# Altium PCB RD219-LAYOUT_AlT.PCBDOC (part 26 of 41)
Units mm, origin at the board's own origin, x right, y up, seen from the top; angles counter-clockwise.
Board outline 209.75 x 159.97 mm, 2 copper layers (TOP, BOTTOM), stack 0 mm thick; 398 components, 199 nets, 1469 pads, 0 vias.
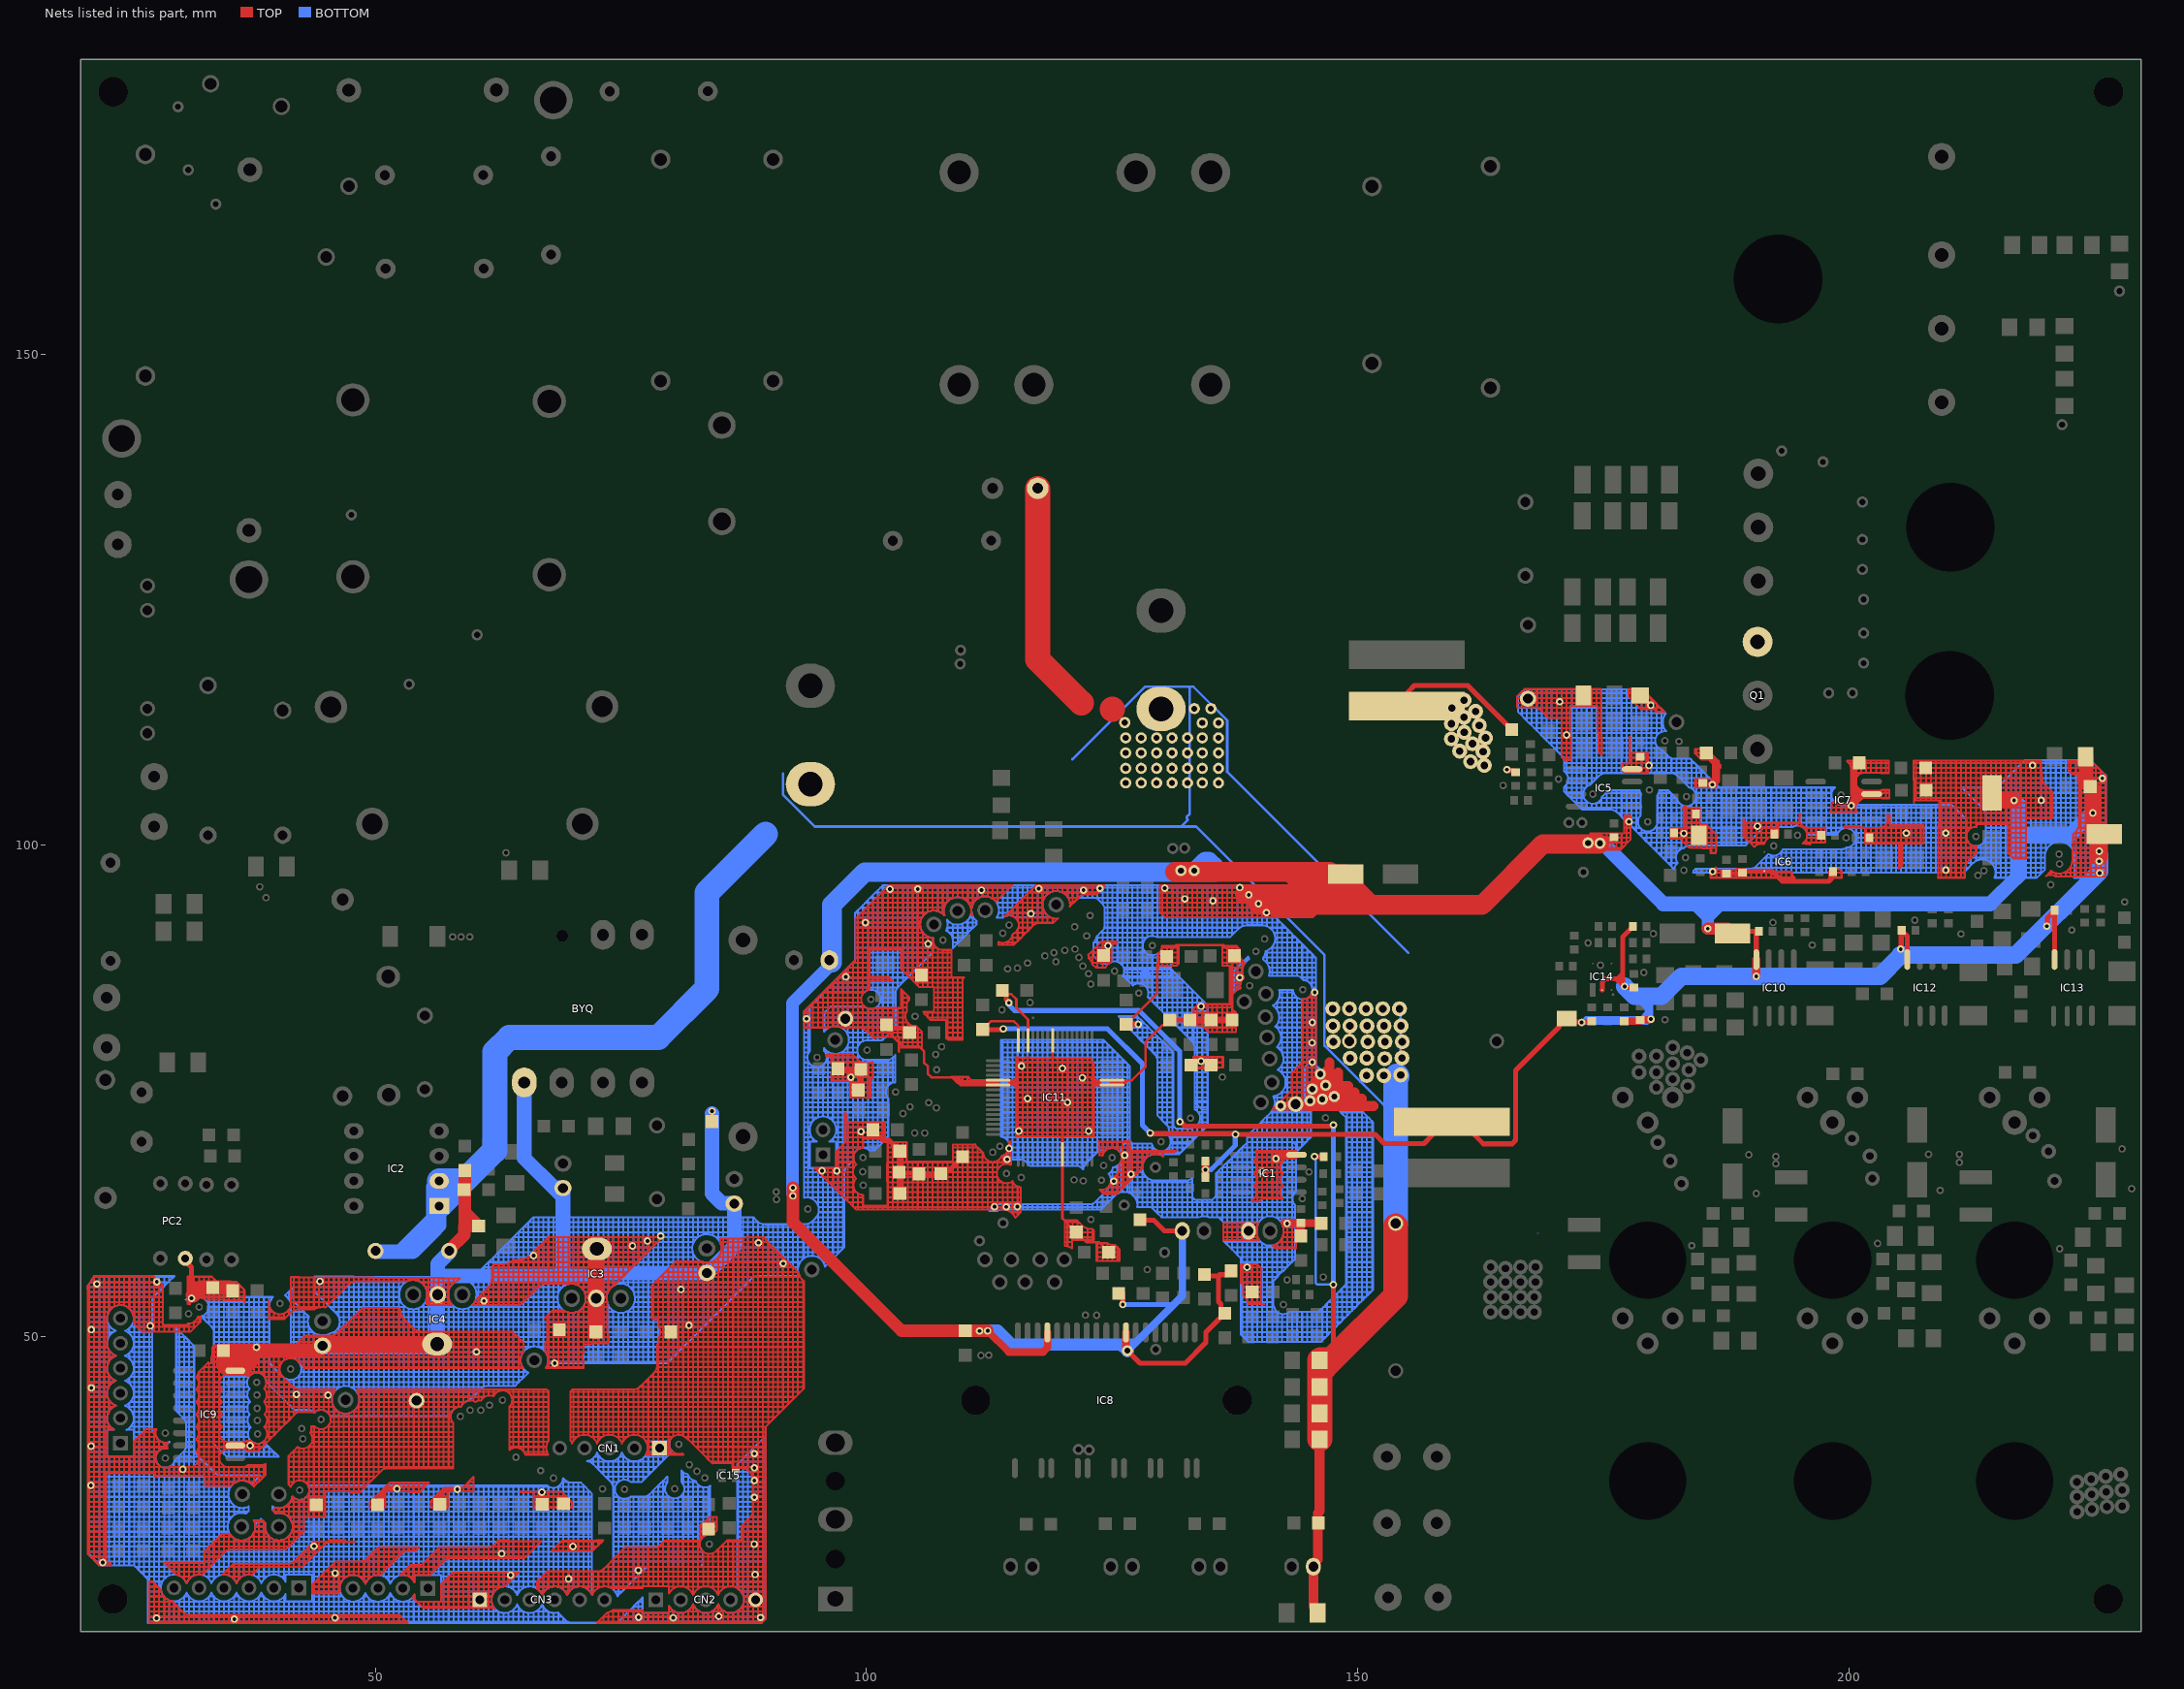
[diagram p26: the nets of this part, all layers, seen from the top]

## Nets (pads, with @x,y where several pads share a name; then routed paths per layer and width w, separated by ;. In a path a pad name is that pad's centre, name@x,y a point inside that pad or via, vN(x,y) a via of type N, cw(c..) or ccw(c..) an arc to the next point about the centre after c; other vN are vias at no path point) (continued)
GND: (continued)
  BOTTOM w0.203: 65.593,59.624 65.593,60.132 ; 65.593,59.624 66.101,59.624 ; 65.593,60.132 65.593,60.64 ; 65.593,60.132 66.101,60.132 ; 65.593,60.64 65.593,61.148 ; 65.593,60.64 66.101,60.64 ; 65.593,61.148 65.593,61.656 ; 65.593,61.148 66.101,61.148 ; 65.593,61.656 66.101,61.656 ; 65.593,61.656 66.101,62.164 ; 65.798,48.956 cw(c66.19,47.61) 66.101,49.009 ; 65.955,24.572 cw(c65.72,23.241) 66.093,24.54 cw(c65.72,23.241) 66.101,24.538 ; 65.955,24.572 66.101,24.572 ; 66.101,20.889 66.101,21.016 ; 66.101,20.889 66.609,20.889 ; 66.101,21.016 66.101,21.524 ; 66.101,21.016 66.609,21.016 ; 66.101,21.524 66.609,21.524 ; 66.101,21.524 66.101,21.944 ; 66.101,24.538 cw(c65.72,23.241) 66.607,24.261 cw(c65.72,23.241) 66.609,24.259 ; 66.101,24.538 66.101,24.572 ; 66.101,24.572 66.101,25.08 ; 66.101,24.572 66.609,24.572 ; 66.101,25.08 66.101,25.588 ; 66.101,25.08 66.609,25.08 ; 66.101,25.588 66.101,26.096 ; 66.101,25.588 66.609,25.588 ; 66.101,26.096 66.101,26.604 ; 66.101,26.096 66.609,26.096 ; 66.101,26.604 66.101,27.112 ; 66.101,26.604 66.609,26.604 ; 66.101,27.112 66.101,27.62 ; 66.101,27.112 66.609,27.112 ; 66.101,27.62 66.101,28.128 ; 66.101,27.62 66.609,27.62 ; 66.101,28.128 66.101,28.636 ; 66.101,28.128 66.609,28.128 ; 66.101,28.636 66.101,29.144 ; 66.101,28.636 66.609,28.636 ; 66.101,29.144 66.101,29.652 ; 66.101,29.144 66.609,29.144 ; 66.101,29.652 66.101,30.16 ; 66.101,29.652 66.609,29.652 ; 66.101,30.16 66.101,30.668 ; 66.101,30.16 66.609,30.16 ; 66.101,30.668 66.101,31.176 ; 66.101,30.668 66.609,30.668 ; 66.101,31.176 66.101,31.684 ; 66.101,31.176 66.609,31.176 ; 66.101,31.684 66.101,32.192 ; 66.101,31.684 66.609,31.684 ; 66.101,32.192 66.101,32.7 ; 66.101,32.192 66.609,32.192 ; 66.101,32.7 66.101,33.208 ; 66.101,32.7 66.609,32.7 ; 66.101,33.208 66.101,33.716 ; 66.101,33.208 66.609,33.208 ; 66.101,33.716 66.101,34.224 ; 66.101,33.716 66.609,33.716 ; 66.101,34.224 66.101,34.732 ; 66.101,34.224 pad.@66.609,34.224 ; 66.101,34.732 66.101,34.866 ; 66.101,34.732 66.609,34.732 ; 66.101,34.866 66.609,34.866 ; 66.101,49.009 cw(c66.19,47.61) 66.582,48.956 ; 66.101,49.009 66.101,49.464 ; 66.101,49.464 66.101,49.972 ; 66.101,49.464 66.609,49.464 ; 66.101,49.972 66.101,50.48 ; 66.101,49.972 66.609,49.972 ; 66.101,50.48 66.101,50.988 ; 66.101,50.48 66.609,50.48 ; 66.101,50.988 66.609,50.988 ; 66.101,50.988 66.101,51.496 ; 66.101,51.496 66.609,51.496 ; 66.101,51.496 66.101,52.004 ; 66.101,52.004 66.101,52.512 ; 66.101,52.004 66.609,52.004 ; 66.101,52.512 66.101,53.02 ; 66.101,52.512 66.609,52.512 ; 66.101,53.02 66.609,53.02 ; 66.101,53.02 66.101,53.528 ; 66.101,53.528 66.101,54.036 ; 66.101,53.528 66.609,53.528 ; 66.101,54.036 66.101,54.544 ; 66.101,54.036 66.609,54.036 ; 66.101,54.544 66.101,55.052 ; 66.101,54.544 66.609,54.544 ; 66.101,55.052 66.101,55.56 ; 66.101,55.052 66.609,55.052 ; 66.101,55.56 66.101,56.068 ; 66.101,55.56 66.609,55.56 ; 66.101,56.068 66.609,56.068 ; 66.101,56.068 66.101,56.195 66.101,56.576 ; 66.101,56.576 66.101,57.084 ; 66.101,56.576 66.609,56.576 ; 66.101,57.084 66.101,57.592 ; 66.101,57.084 66.609,57.084 ; 66.101,57.592 66.609,57.592 ; 66.101,57.592 pad.@66.101,58.1 ; pad.@66.101,58.1 66.609,58.1 ; pad.@66.101,58.1 pad.@66.101,58.608 ; pad.@66.101,58.608 66.101,59.116 ; pad.@66.101,58.608 66.609,58.608 ; 66.101,59.116 66.101,59.624 ; 66.101,59.116 66.609,59.116 ; 66.101,59.624 66.101,60.132 ; 66.101,59.624 66.609,59.624 ; 66.101,60.132 66.101,60.64 ; 66.101,60.132 66.609,60.132 ; 66.101,60.64 66.101,61.148 ; 66.101,60.64 66.609,60.64 ; 66.101,61.148 66.101,61.656 ; 66.101,61.148 66.609,61.148 ; 66.101,61.656 66.609,61.656 ; 66.101,61.656 66.101,62.164 ; 66.101,62.164 66.609,62.164 ; 66.582,48.956 cw(c66.19,47.61) 66.6,48.951 cw(c66.19,47.61) 66.609,48.948 ; 66.582,48.956 66.609,48.956 ; 66.609,20.889 66.609,21.016 ; 66.609,20.889 67.117,20.889 ; 66.609,21.016 66.609,21.524 ; 66.609,21.016 67.117,21.016 ; 66.609,21.524 66.609,22.032 ; 66.609,21.524 67.117,21.524 ; 66.609,22.032 67.117,22.032 ; 66.609,22.032 66.609,22.223 ; 66.609,22.223 ccw(c65.72,23.241) 66.876,22.54 ; 66.609,24.259 66.609,24.572 ; 66.609,24.572 66.609,25.08 ; 66.609,24.572 67.117,24.572 ; 66.609,25.08 66.609,25.588 ; 66.609,25.08 67.117,25.08 ; 66.609,25.588 66.609,26.096 ; 66.609,25.588 67.117,25.588 ; 66.609,26.096 66.609,26.604 ; 66.609,26.096 67.117,26.096 ; 66.609,26.604 66.609,27.112 ; 66.609,26.604 67.117,26.604 ; 66.609,27.112 66.609,27.62 ; 66.609,27.112 67.117,27.112 ; 66.609,27.62 66.609,28.128 ; 66.609,27.62 67.117,27.62 ; 66.609,28.128 66.609,28.636 ; 66.609,28.128 67.117,28.128 ; 66.609,28.636 66.609,29.144 ; 66.609,28.636 67.117,28.636 ; 66.609,29.144 66.609,29.652 ; 66.609,29.144 67.117,29.144 ; 66.609,29.652 66.609,30.16 ; 66.609,29.652 67.117,29.652 ; 66.609,30.16 66.609,30.668 ; 66.609,30.16 67.117,30.16 ; 66.609,30.668 66.609,31.176 ; 66.609,30.668 67.117,30.668 ; 66.609,31.176 66.609,31.684 ; 66.609,31.176 67.117,31.176 ; 66.609,31.684 66.609,32.192 ; 66.609,31.684 67.117,31.684 ; 66.609,32.192 66.609,32.7 ; 66.609,32.192 67.117,32.192 ; 66.609,32.7 66.609,33.208 ; 66.609,32.7 67.117,32.7 ; 66.609,33.208 66.609,33.716 ; 66.609,33.208 67.117,33.208 ; 66.609,33.716 pad.@66.609,34.224 ; 66.609,33.716 67.117,33.716 ; pad.@66.609,34.224 66.609,34.732 ; pad.@66.609,34.224 pad.@67.117,34.224 ; 66.609,34.732 66.609,34.866 ; 66.609,34.732 67.117,34.732 ; 66.609,34.866 67.117,34.866 ; 66.609,48.948 cw(c66.19,47.61) 67.11,48.668 cw(c66.19,47.61) 67.117,48.662 ; 66.609,48.948 66.609,48.956 ; 66.609,48.956 67.117,48.956 ; 66.609,48.956 66.609,49.464 ; 66.609,49.464 66.609,49.972 ; 66.609,49.464 67.117,49.464 ; 66.609,49.972 66.609,50.48 ; 66.609,49.972 67.117,49.972 ; 66.609,50.48 66.609,50.988 ; 66.609,50.48 67.117,50.48 ; 66.609,50.988 66.609,51.496 ; 66.609,50.988 67.117,50.988 ; 66.609,51.496 66.609,52.004 ; 66.609,51.496 67.117,51.496 ; 66.609,52.004 66.609,52.512 ; 66.609,52.004 67.117,52.004 ; 66.609,52.512 66.609,53.02 ; 66.609,52.512 67.117,52.512 ; 66.609,53.02 66.609,53.528 ; 66.609,53.02 67.117,53.02 ; 66.609,53.528 66.609,54.036 ; 66.609,53.528 67.117,53.528 ; 66.609,54.036 66.609,54.544 ; 66.609,54.036 67.117,54.036 ; 66.609,54.544 66.609,55.052 ; 66.609,54.544 67.117,54.544 ; 66.609,55.052 66.609,55.56 ; 66.609,55.052 67.117,55.052 ; 66.609,55.56 66.609,56.068 ; 66.609,55.56 67.117,55.56 ; 66.609,56.068 66.609,56.195 66.609,56.576 ; 66.609,56.068 67.117,56.068 ; 66.609,56.576 66.609,57.084 ; 66.609,56.576 67.117,56.576 ; 66.609,57.084 66.609,57.592 ; 66.609,57.084 67.117,57.084 ; 66.609,57.592 66.609,58.1 ; 66.609,57.592 67.117,57.592 ; 66.609,58.1 66.609,58.608 ; 66.609,58.1 67.117,58.1 ; 66.609,58.608 66.609,59.116 ; 66.609,58.608 67.117,58.608 ; 66.609,59.116 66.609,59.624 ; 66.609,59.116 67.117,59.116 ; 66.609,59.624 66.609,60.132 ; 66.609,59.624 67.117,59.624 ; 66.609,60.132 66.609,60.64 ; 66.609,60.132 67.117,60.132 ; 66.609,60.64 66.609,61.148 ; 66.609,60.64 67.117,60.64 ; 66.609,61.148 66.609,61.656 ; 66.609,61.148 67.117,61.148 ; 66.609,61.656 66.609,62.164 ; 66.609,61.656 67.117,61.656 ; 66.609,62.164 67.117,62.164 ; 66.876,22.54 ccw(c65.72,23.241) 66.879,22.545 ccw(c65.72,23.241) 66.99,22.779 ccw(c68.26,23.241) 67.104,22.54 ; 66.876,22.54 67.104,22.54 ; 67.104,22.54 ccw(c68.26,23.241) 67.114,22.525 ccw(c68.26,23.241) 67.117,22.52 ; 67.117,20.889 67.117,21.016 ; 67.117,20.889 67.625,20.889 ; 67.117,21.016 67.117,21.524 ; 67.117,21.016 67.625,21.016 ; 67.117,21.524 67.117,22.032 ; 67.117,21.524 67.625,21.524 ; 67.117,22.032 67.625,22.032 ; 67.117,22.032 67.117,22.52 ; 67.117,22.52 ccw(c68.26,23.241) 67.625,22.048 67.625,22.032 ; 67.117,24.064 67.117,24.572 ; 67.117,24.064 67.188,24.064 ; 67.117,24.572 67.117,25.08 ; 67.117,24.572 67.625,24.572 ; 67.117,25.08 67.117,25.588 ; 67.117,25.08 67.625,25.08 ; 67.117,25.588 67.117,26.096 ; 67.117,25.588 67.625,25.588 ; 67.117,26.096 67.117,26.604 ; 67.117,26.096 67.625,26.096 ; 67.117,26.604 67.625,26.604 ; 67.117,26.604 67.117,27.112 ; 67.117,27.112 67.117,27.62 ; 67.117,27.112 67.625,27.112 ; 67.117,27.62 67.117,28.128 ; 67.117,27.62 67.625,27.62 ; 67.117,28.128 67.117,28.636 ; 67.117,28.128 67.625,28.128 ; 67.117,28.636 67.117,29.144 ; 67.117,28.636 67.625,28.636 ; 67.117,29.144 67.117,29.652 ; 67.117,29.144 67.625,29.144 ; 67.117,29.652 67.117,30.16 ; 67.117,29.652 67.625,29.652 ; 67.117,30.16 67.117,30.668 ; 67.117,30.16 67.625,30.16 ; 67.117,30.668 67.625,30.668 ; 67.117,30.668 67.117,31.176 ; 67.117,31.176 67.117,31.684 ; 67.117,31.176 67.625,31.176 ; 67.117,31.684 67.117,32.192 ; 67.117,31.684 67.625,31.684 ; 67.117,32.192 67.625,32.192 ; 67.117,32.192 67.117,32.7 ; 67.117,32.7 67.117,33.208 ; 67.117,32.7 67.625,32.7 ; 67.117,33.208 67.117,33.716 ; 67.117,33.208 67.625,33.208 ; 67.117,33.716 67.625,33.716 ; 67.117,33.716 pad.@67.117,34.224 ; pad.@67.117,34.224 67.625,34.224 ; pad.@67.117,34.224 67.117,34.732 ; 67.117,34.732 67.625,34.732 ; 67.117,34.732 67.117,34.866 ; 67.117,48.662 cw(c66.19,47.61) 67.309,48.454 cw(c66.19,47.61) 67.314,48.448 ; 67.117,48.662 67.117,48.956 ; 67.117,48.956 67.117,49.464 ; 67.117,48.956 67.625,48.956 ; 67.117,49.464 67.117,49.972 ; 67.117,49.464 67.625,49.464 ; 67.117,49.972 67.117,50.48 ; 67.117,49.972 67.625,49.972 ; 67.117,50.48 67.117,50.988 ; 67.117,50.48 67.625,50.48 ; 67.117,50.988 67.625,50.988 ; 67.117,50.988 67.117,51.496 ; 67.117,51.496 67.625,51.496 ; 67.117,51.496 67.117,52.004 ; 67.117,52.004 67.117,52.512 ; 67.117,52.004 67.625,52.004 ; 67.117,52.512 67.117,53.02 ; 67.117,52.512 67.625,52.512 ; 67.117,53.02 67.625,53.02 ; 67.117,53.02 67.117,53.528 ; 67.117,53.528 67.117,54.036 ; 67.117,53.528 67.625,53.528 ; 67.117,54.036 67.625,54.036 ; 67.117,54.036 67.117,54.544 ; 67.117,54.544 67.625,54.544 ; 67.117,54.544 67.117,55.052 ; 67.117,55.052 67.625,55.052 ; 67.117,55.052 67.117,55.56 ; 67.117,55.56 67.117,56.068 ; 67.117,55.56 67.625,55.56 ; 67.117,56.068 67.625,56.068 ; 67.117,56.068 67.117,56.195 67.117,56.576 ; 67.117,56.576 67.625,56.576 ; 67.117,56.576 67.117,57.084 ; 67.117,57.084 67.625,57.084 ; 67.117,57.084 67.117,57.592 ; 67.117,57.592 67.625,57.592 ; 67.117,57.592 67.117,58.1 ; 67.117,58.1 67.117,58.608 ; 67.117,58.1 67.625,58.1 ; 67.117,58.608 67.117,59.116 ; 67.117,58.608 67.625,58.608 ; 67.117,59.116 67.117,59.624 ; 67.117,59.116 67.625,59.116 ; 67.117,59.624 67.117,60.132 ; 67.117,59.624 67.625,59.624 ; 67.117,60.132 67.625,60.132 ; 67.117,60.132 67.117,60.64 ; 67.117,60.64 67.625,60.64 ; 67.117,60.64 67.117,61.148 ; 67.117,61.148 67.117,61.656 ; 67.117,61.148 67.625,61.148 ; 67.117,61.656 67.625,61.656 ; 67.117,61.656 67.117,62.164 ; 67.117,62.164 67.625,62.164 ; 67.188,24.064 cw(c68.26,23.241) 67.625,24.434 ; 67.314,48.448 cw(c66.19,47.61) 67.55,47.949 cw(c66.19,47.61) 67.552,47.94 ; 67.314,48.448 67.625,48.448 ; 67.552,47.94 cw(c66.19,47.61) 67.58,47.432 ; 67.552,47.94 67.625,47.94 ; 67.58,47.432 cw(c66.19,47.61) 67.561,47.319 67.625,47.319 ; 67.58,47.432 67.625,47.432 ; 67.625,20.889 67.625,21.016 ; 67.625,20.889 68.133,20.889 ; 67.625,21.016 67.625,21.524 ; 67.625,21.016 68.133,21.016 ; 67.625,21.524 67.625,22.032 ; 67.625,21.524 68.133,21.524 ; 67.625,22.032 67.656,22.032 ; 67.625,24.434 cw(c68.26,23.241) 68.025,24.572 ; 67.625,24.434 67.625,24.572 ; 67.625,24.572 67.625,25.08 ; 67.625,24.572 68.025,24.572 ; 67.625,25.08 67.625,25.588 ; 67.625,25.08 68.133,25.08 ; 67.625,25.588 67.625,26.096 ; 67.625,25.588 68.133,25.588 ; 67.625,26.096 67.625,26.604 ; 67.625,26.096 68.133,26.096 ; 67.625,26.604 68.133,26.604 ; 67.625,26.604 67.625,27.112 ; 67.625,27.112 67.625,27.62 ; 67.625,27.112 68.133,27.112 ; 67.625,27.62 67.625,28.128 ; 67.625,27.62 68.133,27.62 ; 67.625,28.128 67.625,28.636 ; 67.625,28.128 68.133,28.128 ; 67.625,28.636 67.625,29.144 ; 67.625,28.636 68.133,28.636 ; 67.625,29.144 67.625,29.652 ; 67.625,29.144 68.133,29.144 ; 67.625,29.652 67.625,30.16 ; 67.625,29.652 68.133,29.652 ; 67.625,30.16 67.625,30.668 ; 67.625,30.16 68.133,30.16 ; 67.625,30.668 68.133,30.668 ; 67.625,30.668 67.625,31.176 ; 67.625,31.176 67.625,31.684 ; 67.625,31.176 68.133,31.176 ; 67.625,31.684 67.625,32.192 ; 67.625,31.684 68.133,31.684 ; 67.625,32.192 67.625,32.7 ; 67.625,32.192 68.133,32.192 ; 67.625,32.7 67.625,33.208 ; 67.625,32.7 68.133,32.7 ; 67.625,33.208 67.625,33.716 ; 67.625,33.208 68.133,33.208 ; 67.625,33.716 67.625,34.224 ; 67.625,33.716 68.133,33.716 ; 67.625,34.224 68.133,34.224 ; 67.625,34.224 67.625,34.732 ; 67.625,34.732 67.708,34.732 ; 67.625,34.732 67.625,34.777 ; 67.625,34.777 ccw(c68.133,35.618) 67.708,34.732 ; 67.625,47.319 67.625,47.432 ; 67.625,47.319 pad.@68.133,47.319 ; 67.625,47.432 67.625,47.94 ; 67.625,47.432 pad.@68.133,47.432 ; 67.625,47.94 67.625,48.448 ; 67.625,47.94 68.133,47.94 ; 67.625,48.448 67.625,48.956 ; 67.625,48.448 68.133,48.448 ; 67.625,48.956 67.625,49.464 ; 67.625,48.956 68.133,48.956 ; 67.625,49.464 67.625,49.972 ; 67.625,49.464 68.133,49.464 ; 67.625,49.972 67.625,50.48 ; 67.625,49.972 68.133,49.972 ; 67.625,50.48 67.625,50.988 ; 67.625,50.48 68.133,50.48 ; 67.625,50.988 67.625,51.496 ; 67.625,50.988 68.133,50.988 ; 67.625,51.496 67.625,52.004 ; 67.625,51.496 68.133,51.496 ; 67.625,52.004 67.625,52.512 ; 67.625,52.004 68.133,52.004 ; 67.625,52.512 67.625,53.02 ; 67.625,52.512 68.133,52.512 ; 67.625,53.02 68.133,53.02 ; 67.625,53.02 67.625,53.528 ; 67.625,53.528 67.625,54.036 ; 67.625,53.528 68.133,53.528 ; 67.625,54.036 67.625,54.544 ; 67.625,54.036 68.133,54.036 ; 67.625,54.544 67.625,55.052 ; 67.625,54.544 68.133,54.544 ; 67.625,55.052 67.625,55.56 ; 67.625,55.052 68.133,55.052 ; 67.625,55.56 67.625,56.068 ; 67.625,55.56 68.133,55.56 ; 67.625,56.068 68.133,56.068 ; 67.625,56.068 67.625,56.195 67.625,56.576 ; 67.625,56.576 68.133,56.576 ; 67.625,56.576 67.625,57.084 ; 67.625,57.084 67.625,57.592 ; 67.625,57.084 68.133,57.084 ; 67.625,57.592 68.133,57.592 ; 67.625,57.592 67.625,58.1 ; 67.625,58.1 67.625,58.608 ; 67.625,58.1 68.133,58.1 ; 67.625,58.608 67.625,59.116 ; 67.625,58.608 68.133,58.608 ; 67.625,59.116 67.625,59.624 ; 67.625,59.116 68.133,59.116 ; 67.625,59.624 67.625,60.132 ; 67.625,59.624 68.133,59.624 ; 67.625,60.132 67.625,60.64 ; 67.625,60.132 68.133,60.132 ; 67.625,60.64 67.625,61.148 ; 67.625,60.64 68.133,60.64 ; 67.625,61.148 67.625,61.656 ; 67.625,61.148 68.133,61.148 ; 67.625,61.656 67.625,62.164 ; 67.625,61.656 68.133,61.656 ; 67.625,62.164 68.133,62.164 ; 67.656,22.032 ccw(c68.26,23.241) 68.133,21.895 ; 67.708,34.732 ccw(c68.133,35.618) 68.133,34.635 ; 68.025,24.572 cw(c68.26,23.241) 68.133,24.587 ; 68.133,20.889 68.641,20.889 ; 68.133,20.889 68.133,21.016 ; 68.133,21.016 68.641,21.016 ; 68.133,21.016 68.133,21.524 ; 68.133,21.524 68.641,21.524 ; 68.133,21.524 68.133,21.895 ; 68.133,21.895 ccw(c68.26,23.241) 68.142,21.895 ccw(c68.26,23.241) 68.599,21.933 ; 68.133,24.587 cw(c68.26,23.241) 68.495,24.572 ; 68.133,24.587 68.133,25.08 ; 68.133,25.08 68.133,25.588 ; 68.133,25.08 68.641,25.08 ; 68.133,25.588 68.133,26.096 ; 68.133,25.588 68.641,25.588 ; 68.133,26.096 68.133,26.604 ; 68.133,26.096 68.641,26.096 ; 68.133,26.604 68.133,27.112 ; 68.133,26.604 68.641,26.604 ; 68.133,27.112 68.133,27.62 ; 68.133,27.112 68.641,27.112 ; 68.133,27.62 68.133,28.128 ; 68.133,27.62 68.641,27.62 ; 68.133,28.128 68.133,28.636 ; 68.133,28.128 68.641,28.128 ; 68.133,28.636 68.133,29.144 ; 68.133,28.636 68.641,28.636 ; 68.133,29.144 68.133,29.652 ; 68.133,29.144 68.641,29.144 ; 68.133,29.652 68.133,30.16 ; 68.133,29.652 68.641,29.652 ; 68.133,30.16 68.133,30.668 ; 68.133,30.16 68.641,30.16 ; 68.133,30.668 68.133,31.176 ; 68.133,30.668 68.641,30.668 ; 68.133,31.176 68.133,31.684 ; 68.133,31.176 68.641,31.176 ; 68.133,31.684 68.133,32.192 ; 68.133,31.684 68.641,31.684 ; 68.133,32.192 68.133,32.7 ; 68.133,32.192 68.641,32.192 ; 68.133,32.7 68.133,33.208 ; 68.133,32.7 68.641,32.7 ; 68.133,33.208 68.133,33.716 ; 68.133,33.208 68.641,33.208 ; 68.133,33.716 68.133,34.224 ; 68.133,33.716 68.641,33.716 ; 68.133,34.224 68.641,34.224 ; 68.133,34.224 68.133,34.635 ; 68.133,34.635 ccw(c68.133,35.618) 68.558,34.732 ; pad.@68.133,47.319 pad.@68.133,47.432 ; pad.@68.133,47.319 68.641,47.319 ; pad.@68.133,47.432 68.133,47.94 ; pad.@68.133,47.432 68.641,47.432 ; 68.133,47.94 68.133,48.448 ; 68.133,47.94 68.641,47.94 ; 68.133,48.448 68.133,48.956 ; 68.133,48.448 68.641,48.448 ; 68.133,48.956 68.133,49.464 ; 68.133,48.956 68.641,48.956 ; 68.133,49.464 68.133,49.972 ; 68.133,49.464 68.641,49.464 ; 68.133,49.972 68.133,50.48 ; 68.133,49.972 68.641,49.972 ; 68.133,50.48 68.133,50.988 ; 68.133,50.48 68.641,50.48 ; 68.133,50.988 68.133,51.496 ; 68.133,50.988 68.641,50.988 ; 68.133,51.496 68.133,52.004 ; 68.133,51.496 68.641,51.496 ; 68.133,52.004 68.133,52.512 ; 68.133,52.004 68.641,52.004 ; 68.133,52.512 68.133,53.02 ; 68.133,52.512 68.641,52.512 ; 68.133,53.02 68.133,53.528 ; 68.133,53.02 68.641,53.02 ; 68.133,53.528 68.133,54.036 ; 68.133,53.528 68.6,53.528 ; 68.133,54.036 68.133,54.544 ; 68.133,54.036 68.565,54.036 ; 68.133,54.544 68.641,54.544 ; 68.133,54.544 68.133,55.052 ; 68.133,55.052 68.641,55.052 ; 68.133,55.052 68.133,55.56 ; 68.133,55.56 68.133,56.068 ; 68.133,55.56 68.641,55.56 ; 68.133,56.068 68.641,56.068 ; 68.133,56.068 68.133,56.195 68.133,56.576 ; 68.133,56.576 68.641,56.576 ; 68.133,56.576 68.133,57.084 ; 68.133,57.084 68.641,57.084 ; 68.133,57.084 68.133,57.592 ; 68.133,57.592 68.641,57.592 ; 68.133,57.592 68.133,58.1 ; 68.133,58.1 68.133,58.608 ; 68.133,58.1 68.641,58.1 ; 68.133,58.608 68.133,59.116 ; 68.133,58.608 68.641,58.608 ; 68.133,59.116 68.133,59.624 ; 68.133,59.116 68.641,59.116 ; 68.133,59.624 68.133,60.132 ; 68.133,59.624 68.641,59.624 ; 68.133,60.132 68.641,60.132 ; 68.133,60.132 68.133,60.64 ; 68.133,60.64 68.641,60.64 ; 68.133,60.64 68.133,61.148 ; 68.133,61.148 68.133,61.656 ; 68.133,61.148 68.641,61.148 ; 68.133,61.656 68.641,61.656 ; 68.133,61.656 68.133,62.164 ; 68.133,62.164 68.641,62.164 ; 68.495,24.572 cw(c68.26,23.241) 68.633,24.54 cw(c68.26,23.241) 68.641,24.538 ; 68.495,24.572 68.641,24.572 ; 68.558,34.732 ccw(c68.133,35.618) 68.639,34.776 ccw(c68.133,35.618) 68.641,34.777 ; 68.558,34.732 68.641,34.732 ; 68.565,54.036 ccw(c69.991,53.973) 68.564,53.973 68.564,53.846 ccw(c69.991,53.846) 68.6,53.528 ; 68.565,54.036 cw(c69.991,53.973) 68.641,54.435 ; 68.599,21.933 69.008,21.524 ; 68.6,53.528 ccw(c69.991,53.846) 68.641,53.383 ; 68.641,20.889 68.641,21.016 ; 68.641,20.889 69.149,20.889 ; 68.641,21.016 68.641,21.524 ; 68.641,21.016 69.149,21.016 ; 68.641,21.524 69.008,21.524 ; 68.641,24.538 cw(c68.26,23.241) 69.149,24.259 ; 68.641,24.538 68.641,24.572 ; 68.641,24.572 68.641,25.08 ; 68.641,24.572 69.149,24.572 ; 68.641,25.08 68.641,25.588 ; 68.641,25.08 69.149,25.08 ; 68.641,25.588 68.641,26.096 ; 68.641,25.588 69.149,25.588 ; 68.641,26.096 68.641,26.604 ; 68.641,26.096 69.149,26.096 ; 68.641,26.604 69.149,26.604 ; 68.641,26.604 68.641,27.112 ; 68.641,27.112 68.641,27.62 ; 68.641,27.112 69.149,27.112 ; 68.641,27.62 68.641,28.128 ; 68.641,27.62 69.149,27.62 ; 68.641,28.128 68.641,28.636 ; 68.641,28.128 69.149,28.128 ; 68.641,28.636 68.641,29.144 ; 68.641,28.636 69.149,28.636 ; 68.641,29.144 68.641,29.652 ; 68.641,29.144 69.149,29.144 ; 68.641,29.652 68.641,30.16 ; 68.641,29.652 69.149,29.652 ; 68.641,30.16 68.641,30.668 ; 68.641,30.16 69.149,30.16 ; 68.641,30.668 69.149,30.668 ; 68.641,30.668 68.641,31.176 ; 68.641,31.176 68.641,31.684 ; 68.641,31.176 69.149,31.176 ; 68.641,31.684 68.641,32.192 ; 68.641,31.684 69.149,31.684 ; 68.641,32.192 69.149,32.192 ; 68.641,32.192 68.641,32.7 ; 68.641,32.7 68.641,33.208 ; 68.641,32.7 69.149,32.7 ; 68.641,33.208 68.641,33.716 ; 68.641,33.208 69.149,33.208 ; 68.641,33.716 68.641,34.224 ; 68.641,33.716 69.149,33.716 ; 68.641,34.224 69.149,34.224 ; 68.641,34.224 68.641,34.732 ; 68.641,34.732 69.149,34.732 ; 68.641,34.732 68.641,34.777 ; 68.641,34.777 ccw(c68.133,35.618) 69.038,35.234 ccw(c68.133,35.618) 69.04,35.24 ; 68.641,47.319 68.641,47.432 ; 68.641,47.319 69.149,47.319 ; 68.641,47.432 68.641,47.94 ; 68.641,47.432 69.149,47.432 ; 68.641,47.94 68.641,48.448 ; 68.641,47.94 69.149,47.94 ; 68.641,48.448 68.641,48.956 ; 68.641,48.448 69.149,48.448 ; 68.641,48.956 68.641,49.464 ; 68.641,48.956 69.149,48.956 ; 68.641,49.464 68.641,49.972 ; 68.641,49.464 69.149,49.464 ; 68.641,49.972 68.641,50.48 ; 68.641,49.972 69.149,49.972 ; 68.641,50.48 68.641,50.988 ; 68.641,50.48 69.149,50.48 ; 68.641,50.988 68.641,51.496 ; 68.641,50.988 69.149,50.988 ; 68.641,51.496 68.641,52.004 ; 68.641,51.496 69.149,51.496 ; 68.641,52.004 68.641,52.512 ; 68.641,52.004 69.149,52.004 ; 68.641,52.512 68.641,53.02 ; 68.641,52.512 69.149,52.512 ; 68.641,53.02 68.827,53.02 ; 68.641,53.02 68.641,53.383 ; 68.641,53.383 ccw(c69.991,53.846) 68.642,53.381 ccw(c69.991,53.846) 68.827,53.02 ; 68.641,54.435 cw(c69.991,53.973) 68.683,54.544 ; 68.641,54.435 68.641,54.544 ; 68.641,54.544 68.641,55.052 ; 68.641,54.544 68.683,54.544 ; 68.641,55.052 68.641,55.56 ; 68.641,55.052 69.058,55.052 ; 68.641,55.56 68.641,56.068 ; 68.641,55.56 69.149,55.56 ; 68.641,56.068 69.149,56.068 ; 68.641,56.068 68.641,56.195 68.641,56.576 ; 68.641,56.576 69.105,56.576 69.149,56.576 ; 68.641,56.576 68.641,57.084 ; 68.641,57.084 69.105,57.084 69.149,57.084 ; 68.641,57.084 68.641,57.592 ; 68.641,57.592 69.105,57.592 69.149,57.592 ; 68.641,57.592 68.641,58.1 ; 68.641,58.1 68.641,58.608 ; 68.641,58.1 69.105,58.1 69.149,58.1 ; 68.641,58.608 69.105,58.608 69.149,58.608 ; 68.641,58.608 68.641,59.116 ; 68.641,59.116 68.641,59.624 ; 68.641,59.116 69.105,59.116 69.149,59.116 ; 68.641,59.624 68.641,60.132 ; 68.641,59.624 69.105,59.624 69.149,59.624 ; 68.641,60.132 69.105,60.132 69.149,60.132 ; 68.641,60.132 68.641,60.64 ; 68.641,60.64 69.105,60.64 69.149,60.64 ; 68.641,60.64 68.641,61.148 ; 68.641,61.148 68.641,61.656 ; 68.641,61.148 69.105,61.148 69.149,61.148 ; 68.641,61.656 68.641,62.164 ; 68.641,61.656 69.105,61.656 69.149,61.656 ; 68.641,62.164 69.105,62.164 69.149,62.164 ; 68.683,54.544 cw(c69.991,53.973) 69.058,55.052 ; 68.827,53.02 ccw(c69.991,53.846) 69.149,52.693 ; 69.008,21.524 69.149,21.383 ; 69.04,35.24 69.149,35.24 ; 69.058,55.052 cw(c69.991,53.973) 69.149,55.125 ; 69.149,20.889 69.657,20.889 ; 69.149,20.889 69.149,21.016 ; 69.149,21.016 69.149,21.383 ; 69.149,21.016 69.554,21.016 ; 69.149,21.383 69.396,21.136 ; 69.149,24.259 69.149,24.572 ; 69.149,24.572 69.149,25.08 ; 69.149,24.572 69.657,24.572 ; 69.149,25.08 69.149,25.588 ; 69.149,25.08 pad.@69.657,25.08 ; 69.149,25.588 69.149,26.096 ; 69.149,25.588 pad.@69.657,25.588 ; 69.149,26.096 69.149,26.604 ; 69.149,26.096 69.657,26.096 ; 69.149,26.604 69.657,26.604 ; 69.149,26.604 69.149,27.112 ; 69.149,27.112 69.149,27.62 ; 69.149,27.112 69.657,27.112 ; 69.149,27.62 69.149,28.128 ; 69.149,27.62 69.657,27.62 ; 69.149,28.128 69.149,28.636 ; 69.149,28.128 69.657,28.128 ; 69.149,28.636 69.149,29.144 ; 69.149,28.636 69.657,28.636 ; 69.149,29.144 69.149,29.652 ; 69.149,29.144 69.657,29.144 ; 69.149,29.652 69.149,30.16 ; 69.149,29.652 69.657,29.652 ; 69.149,30.16 69.149,30.668 ; 69.149,30.16 69.657,30.16 ; 69.149,30.668 69.149,31.176 ; 69.149,30.668 69.657,30.668 ; 69.149,31.176 69.149,31.684 ; 69.149,31.176 69.657,31.176 ; 69.149,31.684 69.149,32.192 ; 69.149,31.684 69.657,31.684 ; 69.149,32.192 69.657,32.192 ; 69.149,32.192 69.149,32.7 ; 69.149,32.7 69.149,33.208 ; 69.149,32.7 69.657,32.7 ; 69.149,33.208 69.149,33.716 ; 69.149,33.208 69.657,33.208 ; 69.149,33.716 69.149,34.224 ; 69.149,33.716 69.657,33.716 ; 69.149,34.224 69.657,34.224 ; 69.149,34.224 69.149,34.732 ; 69.149,34.732 69.149,35.24 ; 69.149,34.732 69.657,34.732 ; 69.149,35.24 69.149,35.587 ; 69.149,35.24 69.612,35.24 ; 69.149,47.319 69.149,47.432 ; 69.149,47.319 69.657,47.319 ; 69.149,47.432 69.149,47.94 ; 69.149,47.432 69.657,47.432 ; 69.149,47.94 69.149,48.448 ; 69.149,47.94 69.657,47.94 ; 69.149,48.448 69.149,48.956 ; 69.149,48.448 69.657,48.448 ; 69.149,48.956 69.149,49.464 ; 69.149,48.956 69.657,48.956 ; 69.149,49.464 69.149,49.972 ; 69.149,49.464 69.657,49.464 ; 69.149,49.972 69.149,50.48 ; 69.149,49.972 69.657,49.972 ; 69.149,50.48 69.149,50.988 ; 69.149,50.48 69.657,50.48 ; 69.149,50.988 69.149,51.496 ; 69.149,50.988 69.657,50.988 ; 69.149,51.496 69.149,52.004 ; 69.149,51.496 69.657,51.496 ; 69.149,52.004 69.149,52.512 ; 69.149,52.004 69.657,52.004 ; 69.149,52.512 69.483,52.512 ; 69.149,52.512 69.149,52.693 ; 69.149,52.693 ccw(c69.991,53.846) 69.152,52.691 ccw(c69.991,53.846) 69.483,52.512 ; 69.149,55.125 cw(c69.991,53.973) 69.646,55.357 cw(c69.991,53.973) 69.657,55.36 ; 69.149,55.125 69.149,55.56 ; 69.149,55.56 69.149,56.068 ; 69.149,55.56 69.657,55.56 ; 69.149,56.068 69.657,56.068 ; 69.149,56.068 69.149,56.195 69.149,56.576 ; 69.149,56.576 69.657,56.576 ; 69.149,56.576 69.149,57.084 ; 69.149,57.084 69.657,57.084 ; 69.149,57.084 69.149,57.592 ; 69.149,57.592 69.149,58.1 ; 69.149,57.592 69.657,57.592 ; 69.149,58.1 69.149,58.608 ; 69.149,58.1 69.657,58.1 ; 69.149,58.608 69.149,59.116 ; 69.149,58.608 69.657,58.608 ; 69.149,59.116 69.149,59.624 ; 69.149,59.116 69.657,59.116 ; 69.149,59.624 69.149,60.132 ; 69.149,59.624 69.657,59.624 ; 69.149,60.132 69.657,60.132 ; 69.149,60.132 69.149,60.64 ; 69.149,60.64 69.657,60.64 ; 69.149,60.64 69.149,61.148 ; 69.149,61.148 69.149,61.656 ; 69.149,61.148 69.657,61.148 ; 69.149,61.656 69.149,62.164 ; 69.149,61.656 69.657,61.656 ; 69.149,62.164 69.657,62.164 ; 69.396,21.136 ccw(c69.911,21.651) 69.554,21.016 ; 69.396,21.136 ccw(c69.911,21.651) 69.554,21.016 ; 69.483,52.512 ccw(c69.991,53.846) 69.657,52.458 ; 69.554,21.016 ccw(c69.911,21.651) 69.657,20.968 ; 69.554,21.016 ccw(c69.911,21.651) 69.657,20.968 ; 69.612,35.24 ccw(c70.038,36.256) 69.657,35.222 ; 69.612,35.24 ccw(c70.038,36.256) 69.657,35.222 ; 69.612,35.24 cw(c70.038,36.256) 69.259,35.477 ccw(c70.038,36.256) 69.612,35.24 ; 69.657,20.889 74.737,20.889 ; 69.657,20.889 69.657,20.968 ; 69.657,20.968 ccw(c69.911,21.651) 69.911,20.922 ; 69.657,20.968 ccw(c69.911,21.651) 69.911,20.922 ; 69.657,23.962 cw(c70.8,23.241) 69.728,24.064 ; 69.657,23.962 69.657,24.064 ; 69.657,24.064 69.657,24.572 ; 69.657,24.064 69.728,24.064 ; 69.657,24.572 pad.@69.657,25.08 ; 69.657,24.572 70.165,24.572 ; pad.@69.657,25.08 pad.@69.657,25.588 ; pad.@69.657,25.08 70.165,25.08 ; pad.@69.657,25.588 69.657,26.096 ; pad.@69.657,25.588 70.165,25.588 ; 69.657,26.096 69.657,26.604 ; 69.657,26.096 70.165,26.096 ; 69.657,26.604 70.165,26.604 ; 69.657,26.604 69.657,27.112 ; 69.657,27.112 69.657,27.62 ; 69.657,27.112 70.165,27.112 ; 69.657,27.62 69.657,28.128 ; 69.657,27.62 70.165,27.62 ; 69.657,28.128 69.657,28.636 ; 69.657,28.128 70.165,28.128 ; 69.657,28.636 69.657,29.144 ; 69.657,28.636 pad.@70.165,28.636 ; 69.657,29.144 69.657,29.652 ; 69.657,29.144 70.165,29.144 ; 69.657,29.652 69.657,30.16 ; 69.657,29.652 70.165,29.652 ; 69.657,30.16 69.657,30.668 ; 69.657,30.16 70.165,30.16 ; 69.657,30.668 70.165,30.668 ; 69.657,30.668 69.657,31.176 ; 69.657,31.176 69.657,31.684 ; 69.657,31.176 70.165,31.176 ; 69.657,31.684 69.657,32.192 ; 69.657,31.684 70.165,31.684 ; 69.657,32.192 70.165,32.192 ; 69.657,32.192 69.657,32.7 ; 69.657,32.7 69.657,33.208 ; 69.657,32.7 70.165,32.7 ; 69.657,33.208 69.657,33.716 ; 69.657,33.208 70.165,33.208 ; 69.657,33.716 69.657,34.224 ; 69.657,33.716 70.165,33.716 ; 69.657,34.224 70.165,34.224 ; 69.657,34.224 69.657,34.732 ; 69.657,34.732 70.165,34.732 ; 69.657,34.732 69.657,35.222 ; 69.657,35.222 ccw(c70.038,36.256) 69.661,35.221 ; 69.657,35.222 ccw(c70.038,36.256) 69.661,35.221 ; 69.657,47.319 69.657,47.432 ; 69.657,47.319 70.165,47.319 ; 69.657,47.432 69.657,47.94 ; 69.657,47.432 70.165,47.432 ; 69.657,47.94 69.657,48.448 ; 69.657,47.94 70.165,47.94 ; 69.657,48.448 69.657,48.956 ; 69.657,48.448 70.165,48.448 ; 69.657,48.956 69.657,49.464 ; 69.657,48.956 70.165,48.956 ; 69.657,49.464 69.657,49.972 ; 69.657,49.464 70.165,49.464 ; 69.657,49.972 69.657,50.48 ; 69.657,49.972 70.165,49.972 ; 69.657,50.48 69.657,50.988 ; 69.657,50.48 70.165,50.48 ; 69.657,50.988 69.657,51.496 ; 69.657,50.988 70.165,50.988 ; 69.657,51.496 69.657,52.004 ; 69.657,51.496 70.165,51.496 ; 69.657,52.004 70.165,52.004 ; 69.657,52.004 69.657,52.458 ; 69.657,52.458 ccw(c69.991,53.846) 70.165,52.429 ; 69.657,55.36 cw(c69.991,53.973) 69.991,55.4 cw(c69.991,53.973) 70.165,55.389 ; 69.657,55.36 69.657,55.56 ; 69.657,55.56 69.657,56.068 ; 69.657,55.56 70.165,55.56 ; 69.657,56.068 69.657,56.195 69.657,56.576 ; 69.657,56.068 70.165,56.068 ; 69.657,56.576 69.657,57.084 ; 69.657,56.576 70.165,56.576 ; 69.657,57.084 69.657,57.592 ; 69.657,57.084 70.165,57.084 ; 69.657,57.592 69.657,58.1 ; 69.657,57.592 70.165,57.592 ; 69.657,58.1 69.657,58.608 ; 69.657,58.1 70.165,58.1 ; 69.657,58.608 69.657,59.116 ; 69.657,58.608 70.165,58.608 ; 69.657,59.116 69.657,59.624 ; 69.657,59.116 70.165,59.116 ; 69.657,59.624 69.657,60.132 ; 69.657,59.624 70.165,59.624 ; 69.657,60.132 69.657,60.64 ; 69.657,60.132 70.165,60.132 ; 69.657,60.64 69.657,61.148 ; 69.657,60.64 70.165,60.64 ; 69.657,61.148 69.657,61.656 ; 69.657,61.148 70.165,61.148 ; 69.657,61.656 69.657,62.164 ; 69.657,61.656 70.165,61.656 ; 69.657,62.164 70.165,62.164 ; 69.661,35.221 ccw(c70.038,36.256) 70.038,35.154 ; 69.661,35.221 ccw(c70.038,36.256) 70.038,35.154 ; 69.728,24.064 cw(c70.8,23.241) 70.165,24.434 ; 69.911,20.922 74.356,20.922 ; 70.038,35.154 70.165,35.154 ; 70.165,24.434 cw(c70.8,23.241) 70.565,24.572 ; 70.165,24.434 70.165,24.572 ; 70.165,24.572 70.165,25.08 ; 70.165,24.572 70.565,24.572 ; 70.165,25.08 70.673,25.08 ; 70.165,25.08 70.165,25.588 ; 70.165,25.588 70.165,26.096 ; 70.165,25.588 70.673,25.588 ; 70.165,26.096 70.165,26.604 ; 70.165,26.096 70.673,26.096 ; 70.165,26.604 70.673,26.604 ; 70.165,26.604 70.165,27.112 ; 70.165,27.112 70.165,27.62 ; 70.165,27.112 70.673,27.112 ; 70.165,27.62 70.165,28.128 ; 70.165,27.62 70.673,27.62 ; 70.165,28.128 pad.@70.165,28.636 ; 70.165,28.128 70.673,28.128 ; pad.@70.165,28.636 70.673,28.636 ; pad.@70.165,28.636 70.165,29.144 ; 70.165,29.144 70.165,29.652 ; 70.165,29.144 70.673,29.144 ; 70.165,29.652 70.165,30.16 ; 70.165,29.652 70.673,29.652 ; 70.165,30.16 70.165,30.668 ; 70.165,30.16 70.673,30.16 ; 70.165,30.668 70.165,31.176 ; 70.165,30.668 70.673,30.668 ; 70.165,31.176 70.165,31.684 ; 70.165,31.176 70.673,31.176 ; 70.165,31.684 70.165,32.192 ; 70.165,31.684 70.673,31.684 ; 70.165,32.192 70.673,32.192 ; 70.165,32.192 70.165,32.7 ; 70.165,32.7 70.165,33.208 ; 70.165,32.7 70.673,32.7 ; 70.165,33.208 70.165,33.716 ; 70.165,33.208 70.673,33.208 ; 70.165,33.716 70.165,34.224 ; 70.165,33.716 70.673,33.716 ; 70.165,34.224 70.165,34.732 ; 70.165,34.224 70.673,34.224 ; 70.165,34.732 70.673,34.732 ; 70.165,34.732 70.165,35.154 ; 70.165,35.154 70.673,35.154 ; 70.165,47.319 70.165,47.432 ; 70.165,47.319 70.673,47.319 ; 70.165,47.432 70.165,47.94 ; 70.165,47.432 70.673,47.432 ; 70.165,47.94 70.165,48.448 ; 70.165,47.94 70.673,47.94 ; 70.165,48.448 70.165,48.956 ; 70.165,48.448 70.673,48.448 ; 70.165,48.956 70.165,49.464 ; 70.165,48.956 70.673,48.956 ; 70.165,49.464 70.165,49.972 ; 70.165,49.464 70.673,49.464 ; 70.165,49.972 70.165,50.48 ; 70.165,49.972 70.673,49.972 ; 70.165,50.48 70.165,50.988 ; 70.165,50.48 70.673,50.48 ; 70.165,50.988 70.165,51.496 ; 70.165,50.988 70.673,50.988 ; 70.165,51.496 70.165,52.004 ; 70.165,51.496 70.673,51.496 ; 70.165,52.004 70.673,52.004 ; 70.165,52.004 70.165,52.429 ; 70.165,52.429 ccw(c69.991,53.846) 70.499,52.512 ; 70.165,55.389 cw(c69.991,53.973) 70.673,55.226 ; 70.165,55.389 70.165,55.56 ; 70.165,55.56 70.165,56.068 ; 70.165,55.56 70.673,55.56 ; 70.165,56.068 70.165,56.195 70.165,56.576 ; 70.165,56.068 70.673,56.068 ; 70.165,56.576 70.165,57.084 ; 70.165,56.576 70.673,56.576 ; 70.165,57.084 70.165,57.592 ; 70.165,57.084 70.673,57.084 ; 70.165,57.592 70.165,58.1 ; 70.165,57.592 70.673,57.592 ; 70.165,58.1 70.165,58.608 ; 70.165,58.1 70.673,58.1 ; 70.165,58.608 70.165,59.116 ; 70.165,58.608 70.673,58.608 ; 70.165,59.116 70.165,59.624 ; 70.165,59.116 70.673,59.116 ; 70.165,59.624 70.165,60.132 ; 70.165,59.624 70.673,59.624 ; 70.165,60.132 70.165,60.64 ; 70.165,60.132 70.673,60.132 ; 70.165,60.64 70.165,61.148 ; 70.165,60.64 70.673,60.64 ; 70.165,61.148 70.165,61.656 ; 70.165,61.148 70.673,61.148 ; 70.165,61.656 70.165,62.164 ; 70.165,61.656 70.673,61.656 ; 70.165,62.164 70.673,62.164 ; 70.499,52.512 ccw(c69.991,53.846) 70.502,52.513 ccw(c69.991,53.846) 70.673,52.592 ; 70.499,52.512 70.673,52.512 ; 70.565,24.572 cw(c70.8,23.241) 70.673,24.587 ; 70.673,24.587 cw(c70.8,23.241) 71.035,24.572 ; 70.673,24.587 70.673,25.08 ; 70.673,25.08 70.673,25.588 ; 70.673,25.08 71.181,25.08 ; 70.673,25.588 70.673,26.096 ; 70.673,25.588 71.181,25.588 ; 70.673,26.096 70.673,26.604 ; 70.673,26.096 71.181,26.096 ; 70.673,26.604 70.673,27.112 ; 70.673,26.604 71.181,26.604 ; 70.673,27.112 70.673,27.62 ; 70.673,27.112 71.181,27.112 ; 70.673,27.62 70.673,28.128 ; 70.673,27.62 71.181,27.62 ; 70.673,28.128 70.673,28.636 ; 70.673,28.128 71.181,28.128 ; 70.673,28.636 70.673,29.144 ; 70.673,28.636 71.181,28.636 ; 70.673,29.144 70.673,29.652 ; 70.673,29.144 71.181,29.144 ; 70.673,29.652 70.673,30.16 ; 70.673,29.652 71.181,29.652 ; 70.673,30.16 70.673,30.668 ; 70.673,30.16 71.181,30.16 ; 70.673,30.668 70.673,31.176 ; 70.673,30.668 71.181,30.668 ; 70.673,31.176 70.673,31.684 ; 70.673,31.176 71.181,31.176 ; 70.673,31.684 70.673,32.192 ; 70.673,31.684 71.181,31.684 ; 70.673,32.192 70.673,32.7 ; 70.673,32.192 71.181,32.192 ; 70.673,32.7 70.673,33.208 ; 70.673,32.7 71.181,32.7 ; 70.673,33.208 70.673,33.716 ; 70.673,33.208 71.181,33.208 ; 70.673,33.716 70.673,34.224 ; 70.673,33.716 71.181,33.716 ; 70.673,34.224 70.673,34.732 ; 70.673,34.224 71.181,34.224 ; 70.673,34.732 71.181,34.732 ; 70.673,34.732 70.673,35.154 ; 70.673,35.154 70.935,35.154 71.181,34.908 ; 70.673,47.319 70.673,47.432 ; 70.673,47.319 71.181,47.319 ; 70.673,47.432 70.673,47.94 ; 70.673,47.432 71.181,47.432 ; 70.673,47.94 70.673,48.448 ; 70.673,47.94 71.181,47.94 ; 70.673,48.448 70.673,48.956 ; 70.673,48.448 71.181,48.448 ; 70.673,48.956 70.673,49.464 ; 70.673,48.956 71.181,48.956 ; 70.673,49.464 70.673,49.972 ; 70.673,49.464 71.181,49.464 ; 70.673,49.972 70.673,50.48 ; 70.673,49.972 71.181,49.972 ; 70.673,50.48 70.673,50.988 ; 70.673,50.48 71.181,50.48 ; 70.673,50.988 70.673,51.496 ; 70.673,50.988 71.181,50.988 ; 70.673,51.496 70.673,52.004 ; 70.673,51.496 71.181,51.496 ; 70.673,52.004 70.673,52.512 ; 70.673,52.004 71.181,52.004 ; 70.673,52.512 71.181,52.512 ; 70.673,52.512 70.673,52.592 ; 70.673,52.592 ccw(c69.991,53.846) 71.155,53.02 ; 70.673,55.226 cw(c69.991,53.973) 70.683,55.221 cw(c69.991,53.973) 70.924,55.052 ; 70.673,55.226 70.673,55.56 ; 70.673,55.56 70.673,56.068 ; 70.673,55.56 71.181,55.56 ; 70.673,56.068 70.673,56.195 70.673,56.576 ; 70.673,56.068 71.181,56.068 ; 70.673,56.576 70.673,57.084 ; 70.673,56.576 71.181,56.576 ; 70.673,57.084 70.673,57.592 ; 70.673,57.084 71.181,57.084 ; 70.673,57.592 70.673,58.1 ; 70.673,57.592 71.181,57.592 ; 70.673,58.1 70.673,58.608 ; 70.673,58.1 71.181,58.1 ; 70.673,58.608 70.673,59.116 ; 70.673,58.608 IC3.4@71.181,58.608 ; 70.673,59.116 70.673,59.624 ; 70.673,59.116 IC3.4@71.181,59.116 ; 70.673,59.624 70.673,60.132 ; 70.673,59.624 71.181,59.624 ; 70.673,60.132 70.673,60.64 ; 70.673,60.132 71.181,60.132 ; 70.673,60.64 70.673,61.148 ; 70.673,60.64 71.181,60.64 ; 70.673,61.148 70.673,61.656 ; 70.673,61.148 71.181,61.148 ; 70.673,61.656 70.673,62.164 ; 70.673,61.656 71.181,61.656 ; 70.673,62.164 71.181,62.164 ; 70.924,55.052 cw(c69.991,53.973) 71.174,54.771 cw(c69.991,53.973) 71.181,54.76 ; 70.924,55.052 71.181,55.052 ; 71.035,24.572 cw(c70.8,23.241) 71.173,24.54 cw(c70.8,23.241) 71.181,24.538 ; 71.035,24.572 71.181,24.572 ; 71.155,53.02 ccw(c69.991,53.846) 71.181,53.058 ; 71.155,53.02 71.181,53.02 ; 71.181,24.538 cw(c70.8,23.241) 71.687,24.261 cw(c70.8,23.241) 71.689,24.259 ; 71.181,24.538 71.181,24.572 ; 71.181,24.572 71.181,25.08 ; 71.181,24.572 71.689,24.572 ; 71.181,25.08 71.181,25.588 ; 71.181,25.08 71.689,25.08 ; 71.181,25.588 71.181,26.096 ; 71.181,25.588 71.689,25.588 ; 71.181,26.096 71.181,26.604 ; 71.181,26.096 71.689,26.096 ; 71.181,26.604 71.181,27.112 ; 71.181,26.604 71.689,26.604 ; 71.181,27.112 71.181,27.62 ; 71.181,27.112 71.689,27.112 ; 71.181,27.62 71.181,28.128 ; 71.181,27.62 71.689,27.62 ; 71.181,28.128 71.181,28.636 ; 71.181,28.128 71.689,28.128 ; 71.181,28.636 71.181,29.144 ; 71.181,28.636 71.689,28.636 ; 71.181,29.144 71.181,29.652 ; 71.181,29.144 71.689,29.144 ; 71.181,29.652 71.181,30.16 ; 71.181,29.652 71.689,29.652 ; 71.181,30.16 71.181,30.668 ; 71.181,30.16 71.689,30.16 ; 71.181,30.668 71.181,31.176 ; 71.181,30.668 71.689,30.668 ; 71.181,31.176 71.181,31.684 ; 71.181,31.176 71.689,31.176 ; 71.181,31.684 71.181,32.192 ; 71.181,31.684 71.689,31.684 ; 71.181,32.192 71.181,32.7 ; 71.181,32.192 71.689,32.192 ; 71.181,32.7 71.181,33.208 ; 71.181,32.7 71.689,32.7 ; 71.181,33.208 71.181,33.716 ; 71.181,33.208 71.689,33.208 ; 71.181,33.716 71.181,34.224 ; 71.181,33.716 71.689,33.716 ; 71.181,34.224 71.181,34.732 ; 71.181,34.224 71.689,34.224 ; 71.181,34.732 71.357,34.732 ; 71.181,34.732 71.181,34.908 ; 71.181,34.908 71.357,34.732 ; 71.181,47.319 71.181,47.432 ; 71.181,47.319 71.689,47.319 ; 71.181,47.432 71.181,47.94 ; 71.181,47.432 71.689,47.432 ; 71.181,47.94 71.181,48.448 ; 71.181,47.94 71.689,47.94 ; 71.181,48.448 71.181,48.956 ; 71.181,48.448 71.689,48.448 ; 71.181,48.956 71.181,49.464 ; 71.181,48.956 71.689,48.956 ; 71.181,49.464 71.181,49.972 ; 71.181,49.464 71.689,49.464 ; 71.181,49.972 71.181,50.48 ; 71.181,49.972 71.689,49.972 ; 71.181,50.48 71.181,50.988 ; 71.181,50.48 71.689,50.48 ; 71.181,50.988 71.181,51.496 ; 71.181,50.988 71.689,50.988 ; 71.181,51.496 71.181,52.004 ; 71.181,51.496 71.689,51.496 ; 71.181,52.004 71.181,52.512 ; 71.181,52.004 71.689,52.004 ; 71.181,52.512 71.181,53.02 ; 71.181,52.512 71.689,52.512 ; 71.181,53.02 71.689,53.02 ; 71.181,53.02 71.181,53.058 ; 71.181,53.058 ccw(c69.991,53.846) 71.382,53.524 ccw(c69.991,53.846) 71.382,53.528 ; 71.181,54.76 cw(c69.991,53.973) 71.295,54.553 cw(c69.991,53.973) 71.299,54.544 ; 71.181,54.76 71.181,55.052 ; 71.181,55.052 71.181,55.56 ; 71.181,55.052 71.689,55.052 ; 71.181,55.56 71.181,56.068 ; 71.181,55.56 71.689,55.56 ; 71.181,56.068 71.181,56.195 71.181,56.576 ; 71.181,56.068 71.689,56.068 ; 71.181,56.576 71.181,57.084 ; 71.181,56.576 71.689,56.576 ; 71.181,57.084 71.181,57.592 ; 71.181,57.084 71.689,57.084 ; 71.181,57.592 71.181,58.1 ; 71.181,57.592 71.689,57.592 ; 71.181,58.1 IC3.4@71.181,58.608 ; 71.181,58.1 IC3.4@71.689,58.1 ; IC3.4@71.181,58.608 IC3.4@71.689,58.608 ; IC3.4@71.181,58.608 IC3.4@71.181,59.116 ; IC3.4@71.181,59.116 71.181,59.624 ; IC3.4@71.181,59.116 IC3.4@71.689,59.116 ; 71.181,59.624 71.181,60.132 ; 71.181,59.624 IC3.4@71.689,59.624 ; 71.181,60.132 71.181,60.64 ; 71.181,60.132 71.689,60.132 ; 71.181,60.64 71.181,61.148 ; 71.181,60.64 71.689,60.64 ; 71.181,61.148 71.181,61.656 ; 71.181,61.148 71.689,61.148 ; 71.181,61.656 71.181,62.164 ; 71.181,61.656 71.689,61.656 ; 71.181,62.164 71.689,62.164 ; 71.299,54.544 cw(c69.991,53.973) 71.417,54.036 ; 71.299,54.544 71.689,54.544 ; 71.357,34.732 71.689,34.4 ; 71.382,53.528 ccw(c69.991,53.846) 71.418,53.846 71.418,53.973 ccw(c69.991,53.973) 71.417,54.036 ; 71.382,53.528 71.689,53.528 ; 71.417,54.036 IC3.2@71.689,54.036 ; 71.689,24.259 cw(c70.8,23.241) 71.865,24.073 cw(c70.8,23.241) 71.872,24.064 ; 71.689,24.259 71.689,24.572 ; 71.689,24.572 71.689,25.08 ; 71.689,24.572 72.034,24.572 ; 71.689,25.08 71.689,25.588 ; 71.689,25.08 72.034,25.08 ; 71.689,25.588 71.689,26.096 ; 71.689,25.588 72.034,25.588 ; 71.689,26.096 71.689,26.604 ; 71.689,26.096 72.034,26.096 ; 71.689,26.604 71.689,27.112 ; 71.689,26.604 72.034,26.604 ; 71.689,27.112 71.689,27.62 ; 71.689,27.112 72.034,27.112 ; 71.689,27.62 71.689,28.128 ; 71.689,27.62 72.034,27.62 ; 71.689,28.128 71.689,28.636 ; 71.689,28.128 72.034,28.128 ; 71.689,28.636 71.689,29.144 ; 71.689,28.636 72.034,28.636 ; 71.689,29.144 71.689,29.652 ; 71.689,29.144 72.034,29.144 ; 71.689,29.652 71.689,30.16 ; 71.689,29.652 72.034,29.652 ; 71.689,30.16 71.689,30.668 ; 71.689,30.16 72.034,30.16 ; 71.689,30.668 71.689,31.176 ; 71.689,30.668 72.034,30.668 ; 71.689,31.176 71.689,31.684 ; 71.689,31.176 72.034,31.176 ; 71.689,31.684 71.689,32.192 ; 71.689,31.684 72.034,31.684 ; 71.689,32.192 71.689,32.7 ; 71.689,32.192 72.034,32.192 ; 71.689,32.7 71.689,33.208 ; 71.689,32.7 72.034,32.7 ; 71.689,33.208 71.689,33.716 ; 71.689,33.208 72.034,33.208 ; 71.689,33.716 71.689,34.224 ; 71.689,33.716 72.034,33.716 ; 71.689,34.224 71.689,34.4 ; 71.689,34.224 71.865,34.224 ; 71.689,34.4 71.865,34.224 ; 71.689,47.319 71.689,47.432 ; 71.689,47.319 72.197,47.319 ; 71.689,47.432 71.689,47.94 ; 71.689,47.432 72.197,47.432 ; 71.689,47.94 71.689,48.448 ; 71.689,47.94 72.197,47.94 ; 71.689,48.448 71.689,48.956 ; 71.689,48.448 72.197,48.448 ; 71.689,48.956 71.689,49.464 ; 71.689,48.956 72.197,48.956 ; 71.689,49.464 71.689,49.972 ; 71.689,49.464 72.197,49.464 ; 71.689,49.972 71.689,50.48 ; 71.689,49.972 72.197,49.972 ; 71.689,50.48 71.689,50.988 ; 71.689,50.48 72.197,50.48 ; 71.689,50.988 71.689,51.496 ; 71.689,50.988 72.197,50.988 ; 71.689,51.496 71.689,52.004 ; 71.689,51.496 72.197,51.496 ; 71.689,52.004 71.689,52.512 ; 71.689,52.004 72.197,52.004 ; 71.689,52.512 71.689,53.02 ; 71.689,52.512 72.197,52.512 ; 71.689,53.02 71.689,53.528 ; 71.689,53.02 72.197,53.02 ; 71.689,53.528 IC3.2@72.197,53.528 ; 71.689,53.528 IC3.2@71.689,54.036 ; IC3.2@71.689,54.036 71.689,54.544 ; IC3.2@71.689,54.036 IC3.2@72.197,54.036 ; 71.689,54.544 71.689,55.052 ; 71.689,54.544 IC3.2@72.197,54.544 ; 71.689,55.052 71.689,55.56 ; 71.689,55.052 72.197,55.052 ; 71.689,55.56 71.689,56.068 ; 71.689,55.56 72.197,55.56 ; 71.689,56.068 71.689,56.195 71.689,56.576 ; 71.689,56.068 72.197,56.068 ; 71.689,56.576 71.689,57.084 ; 71.689,56.576 72.197,56.576 ; 71.689,57.084 71.689,57.592 ; 71.689,57.084 72.197,57.084 ; 71.689,57.592 IC3.4@71.689,58.1 ; 71.689,57.592 72.197,57.592 ; IC3.4@71.689,58.1 IC3.4@71.689,58.608 ; IC3.4@71.689,58.1 IC3.4@72.197,58.1 ; IC3.4@71.689,58.608 IC3.4@72.197,58.608 ; IC3.4@71.689,58.608 IC3.4@71.689,59.116 ; IC3.4@71.689,59.116 IC3.4@71.689,59.624 ; IC3.4@71.689,59.116 IC3.4@72.197,59.116 ; IC3.4@71.689,59.624 71.689,60.132 ; IC3.4@71.689,59.624 IC3.4@72.197,59.624 ; 71.689,60.132 71.689,60.64 ; 71.689,60.132 72.197,60.132 ; 71.689,60.64 71.689,61.148 ; 71.689,60.64 72.197,60.64 ; 71.689,61.148 71.689,61.656 ; 71.689,61.148 72.197,61.148 ; 71.689,61.656 71.689,62.164 ; 71.689,61.656 72.197,61.656 ; 71.689,62.164 72.197,62.164 ; 71.817,37.272 cw(c71.391,36.256) 71.821,37.27 ; 71.817,37.272 cw(c71.391,36.256) 71.821,37.27 ; 71.817,37.272 ccw(c71.391,36.256) 71.582,37.341 cw(c71.391,36.256) 71.817,37.272 ; 71.817,37.272 72.197,37.272 ; 71.821,37.27 cw(c71.391,36.256) 72.17,37.035 ; 71.821,37.27 cw(c71.391,36.256) 72.17,37.035 ; 71.865,34.224 72.034,34.055 72.034,33.716 ; 71.872,24.064 72.034,24.064 ; 72.034,24.064 72.034,24.572 ; 72.034,24.572 72.034,25.08 ; 72.034,25.08 72.034,25.588 ; 72.034,25.588 72.034,26.096 ; 72.034,26.096 72.034,26.604 ; 72.034,26.604 72.034,27.112 ; 72.034,27.112 72.034,27.62 ; 72.034,27.62 72.034,28.128 ; 72.034,28.128 72.034,28.636 ; 72.034,28.636 72.034,29.144 ; 72.034,29.144 72.034,29.652 ; 72.034,29.652 72.034,30.16 ; 72.034,30.16 72.034,30.668 ; 72.034,30.668 72.034,31.176 ; 72.034,31.176 72.034,31.684 ; 72.034,31.684 72.034,32.192 ; 72.034,32.192 72.034,32.7 ; 72.034,32.7 72.034,33.208 ; 72.034,33.208 72.034,33.716 ; 72.171,37.034 72.197,37.008 ; 72.197,37.008 72.441,36.764 ; 72.197,37.008 72.197,37.272 ; 72.197,37.272 72.705,37.272 ; 72.197,37.272 72.197,37.651 ; 72.197,37.651 ccw(c71.308,38.669) 72.326,37.78 ; 72.197,47.319 72.197,47.432 ; 72.197,47.319 72.705,47.319 ; 72.197,47.432 72.197,47.94 ; 72.197,47.432 72.705,47.432 ; 72.197,47.94 72.197,48.448 ; 72.197,47.94 72.705,47.94 ; 72.197,48.448 72.197,48.956 ; 72.197,48.448 72.705,48.448 ; 72.197,48.956 72.197,49.464 ; 72.197,48.956 72.705,48.956 ; 72.197,49.464 72.197,49.972 ; 72.197,49.464 72.705,49.464 ; 72.197,49.972 72.197,50.48 ; 72.197,49.972 72.705,49.972 ; 72.197,50.48 72.197,50.988 ; 72.197,50.48 72.705,50.48 ; 72.197,50.988 72.197,51.496 ; 72.197,50.988 72.705,50.988 ; 72.197,51.496 72.197,52.004 ; 72.197,51.496 72.705,51.496 ; 72.197,52.004 72.197,52.512 ; 72.197,52.004 72.705,52.004 ; 72.197,52.512 72.197,53.02 ; 72.197,52.512 72.705,52.512 ; 72.197,53.02 IC3.2@72.197,53.528 ; 72.197,53.02 72.705,53.02 ; IC3.2@72.197,53.528 IC3.2@72.197,54.036 ; IC3.2@72.197,53.528 IC3.2@72.705,53.528 ; IC3.2@72.197,54.036 IC3.2@72.197,54.544 ; IC3.2@72.197,54.036 72.52,54.036 IC3.2@72.705,54.036 ; IC3.2@72.197,54.544 72.197,55.052 ; IC3.2@72.197,54.544 72.52,54.544 IC3.2@72.705,54.544 ; 72.197,55.052 72.52,55.052 72.705,55.052 ; 72.197,55.052 72.197,55.56 ; 72.197,55.56 72.197,56.068 ; 72.197,55.56 72.52,55.56 72.705,55.56 ; 72.197,56.068 72.52,56.068 72.705,56.068 ; 72.197,56.068 72.197,56.195 72.197,56.576 ; 72.197,56.576 72.197,57.084 ; 72.197,56.576 72.52,56.576 72.705,56.576 ; 72.197,57.084 72.52,57.084 72.705,57.084 ; 72.197,57.084 72.197,57.592 ; 72.197,57.592 IC3.4@72.197,58.1 ; 72.197,57.592 72.52,57.592 72.705,57.592 ; IC3.4@72.197,58.1 72.52,58.1 IC3.4@72.705,58.1 ; IC3.4@72.197,58.1 IC3.4@72.197,58.608 ; IC3.4@72.197,58.608 72.52,58.608 IC3.4@72.705,58.608 ; IC3.4@72.197,58.608 IC3.4@72.197,59.116 ; IC3.4@72.197,59.116 IC3.4@72.197,59.624 ; IC3.4@72.197,59.116 IC3.4@72.705,59.116 ; IC3.4@72.197,59.624 72.197,60.132 ; IC3.4@72.197,59.624 IC3.4@72.705,59.624 ; 72.197,60.132 72.197,60.64 ; 72.197,60.132 72.705,60.132 ; 72.197,60.64 72.197,61.148 ; 72.197,60.64 72.705,60.64 ; 72.197,61.148 72.197,61.656 ; 72.197,61.148 72.705,61.148 ; 72.197,61.656 72.197,62.164 ; 72.197,61.656 72.705,61.656 ; 72.197,62.164 72.705,62.164 ; 72.326,37.78 ccw(c71.308,38.669) 72.578,38.206 ccw(c73.848,38.669) 72.702,37.953 ccw(c73.848,38.669) 72.705,37.948 ; 72.326,37.78 72.705,37.78 ; 72.441,36.764 72.705,36.764 ; 72.441,36.764 72.705,36.5 ; 72.705,36.5 72.705,36.764 ; 72.705,36.5 72.949,36.256 ; 72.705,36.764 72.705,37.272 ; 72.705,36.764 73.213,36.764 ; 72.705,37.272 72.705,37.78 ; 72.705,37.272 73.213,37.272 ; 72.705,37.78 72.705,37.948 ; 72.705,37.78 72.83,37.78 ; 72.705,37.948 ccw(c73.848,38.669) 72.83,37.78 ; 72.705,47.319 72.705,47.432 ; 72.705,47.319 73.213,47.319 ; 72.705,47.432 72.705,47.94 ; 72.705,47.432 73.213,47.432 ; 72.705,47.94 72.705,48.448 ; 72.705,47.94 73.213,47.94 ; 72.705,48.448 72.705,48.956 ; 72.705,48.448 73.213,48.448 ; 72.705,48.956 72.705,49.464 ; 72.705,48.956 73.213,48.956 ; 72.705,49.464 72.705,49.972 ; 72.705,49.464 73.213,49.464 ; 72.705,49.972 72.705,50.48 ; 72.705,49.972 73.213,49.972 ; 72.705,50.48 72.705,50.988 ; 72.705,50.48 73.213,50.48 ; 72.705,50.988 72.705,51.496 ; 72.705,50.988 73.213,50.988 ; 72.705,51.496 72.705,52.004 ; 72.705,51.496 73.213,51.496 ; 72.705,52.004 72.705,52.512 ; 72.705,52.004 73.213,52.004 ; 72.705,52.512 72.705,53.02 ; 72.705,52.512 73.213,52.512 ; 72.705,53.02 IC3.2@72.705,53.528 ; 72.705,53.02 73.213,53.02 ; IC3.2@72.705,53.528 IC3.2@73.213,53.528 ; IC3.2@72.705,53.528 IC3.2@72.705,54.036 ; IC3.2@72.705,54.036 IC3.2@72.705,54.544 ; IC3.2@72.705,54.036 IC3.2@73.213,54.036 ; IC3.2@72.705,54.544 72.705,55.052 ; IC3.2@72.705,54.544 73.213,54.544 ; 72.705,55.052 72.705,55.56 ; 72.705,55.052 73.213,55.052 ; 72.705,55.56 72.705,56.068 ; 72.705,55.56 73.213,55.56 ; 72.705,56.068 72.705,56.38 72.705,56.576 ; 72.705,56.068 73.213,56.068 ; 72.705,56.576 72.705,57.084 ; 72.705,56.576 73.213,56.576 ; 72.705,57.084 72.705,57.592 ; 72.705,57.084 73.213,57.084 ; 72.705,57.592 IC3.4@72.705,58.1 ; 72.705,57.592 73.213,57.592 ; IC3.4@72.705,58.1 IC3.4@72.705,58.608 ; IC3.4@72.705,58.1 IC3.4@73.213,58.1 ; IC3.4@72.705,58.608 IC3.4@73.213,58.608 ; IC3.4@72.705,58.608 IC3.4@72.705,59.116 ; IC3.4@72.705,59.116 IC3.4@72.705,59.624 ; IC3.4@72.705,59.116 IC3.4@73.213,59.116 ; IC3.4@72.705,59.624 72.705,60.132 ; IC3.4@72.705,59.624 IC3.4@73.213,59.624 ; 72.705,60.132 72.705,60.64 ; 72.705,60.132 73.213,60.132 ; 72.705,60.64 72.705,61.148 ; 72.705,60.64 73.213,60.64 ; 72.705,61.148 72.705,61.656 ; 72.705,61.148 73.213,61.148 ; 72.705,61.656 72.705,62.164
